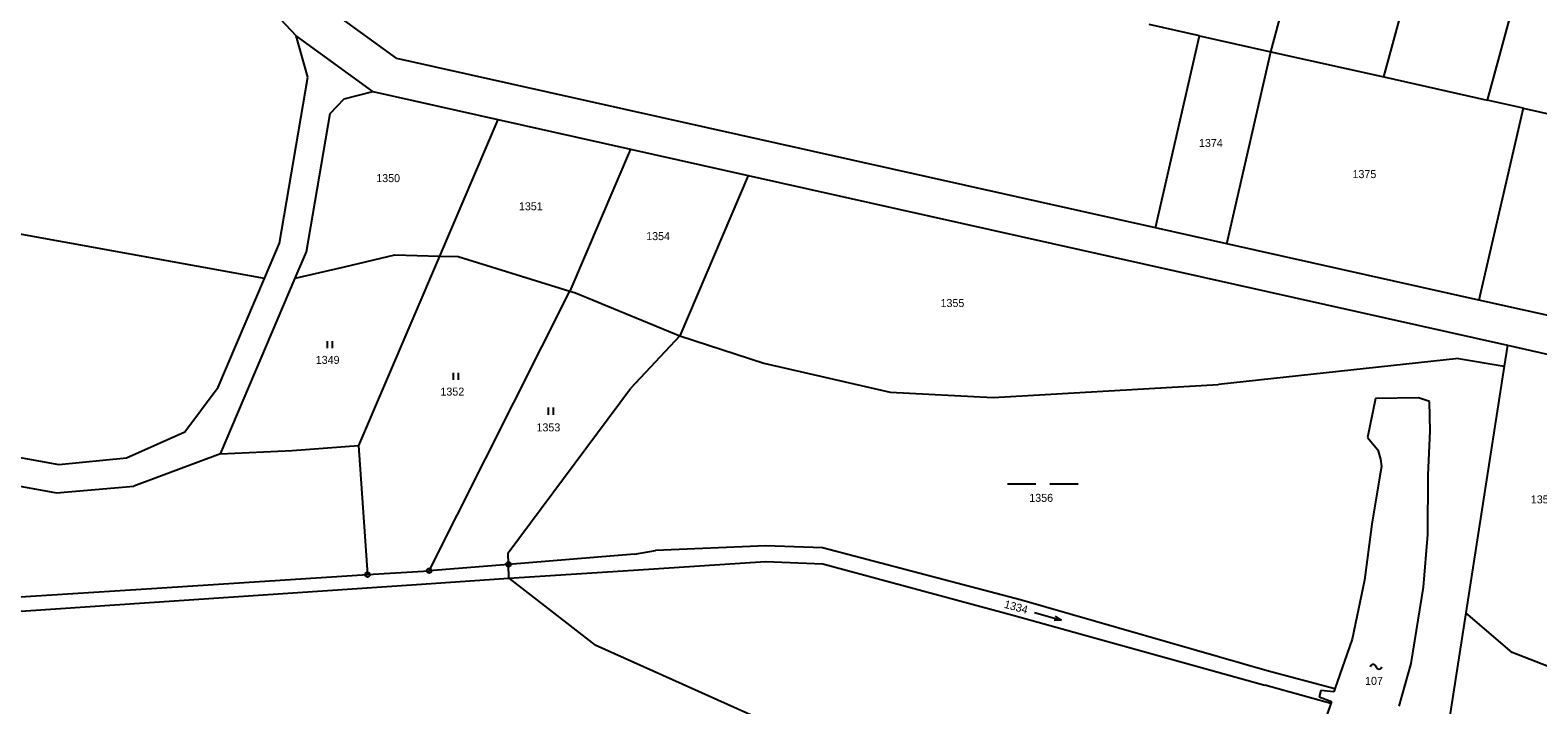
# Model space of a CAD drawing. Extents: x -796130 to -793145, y -1109506 to -1106267.
# Drawn here: x -795165.2 to -794845, y -1107731.2 to -1107587.8 of the extents above; entities that cross this region are included whole.
import ezdxf

# ---------------------------------------------------------------- set-up
doc = ezdxf.new("R2010")
doc.units = 0
for name, color, linetype in [('Vrstva 1', 7, 'Continuous'), ('Vrstva 14', 7, 'Continuous'), ('Vrstva 15', 7, 'Continuous'), ('Vrstva 23', 7, 'Continuous'), ('Vrstva 25', 7, 'Continuous'), ('Vrstva 28', 7, 'Continuous')]:
    doc.layers.add(name, color=color, linetype=linetype)

msp = doc.modelspace()

# ---------------------------------------------------------------- linework, layer by layer
at = {"layer": 'Vrstva 1'}
for p, q in [((-795151.06, -1107543.92), (-795108.76, -1107589.05)), ((-794901.69, -1107592.42), (-794889.91, -1107549.15)), ((-794877.66, -1107597.79), (-794866.67, -1107557.39)), ((-794845.65, -1107565.77), (-794855.7, -1107602.7)), ((-795087.38, -1107593.83), (-795105.91, -1107580.39)), ((-794916.83, -1107589.03), (-794927.52, -1107586.64)), ((-795092.45, -1107600.89), (-795108.76, -1107589.05)), ((-795106.26, -1107597.81), (-795108.76, -1107589.05)), ((-794926.2, -1107629.87), (-794916.83, -1107589.03)), ((-794916.83, -1107589.03), (-794901.69, -1107592.42)), ((-794911.06, -1107633.25), (-794901.69, -1107592.42)), ((-794901.69, -1107592.42), (-794877.66, -1107597.79)), ((-794926.2, -1107629.87), (-795087.38, -1107593.83)), ((-795112.31, -1107633.1), (-795106.26, -1107597.81)), ((-794877.66, -1107597.79), (-794855.7, -1107602.7)), ((-795101.49, -1107605.52), (-795098.55, -1107602.42)), ((-795098.55, -1107602.42), (-795092.45, -1107600.89)), ((-795092.45, -1107600.89), (-795065.91, -1107606.83)), ((-794848.09, -1107604.4), (-794855.7, -1107602.7)), ((-795106.54, -1107634.93), (-795101.49, -1107605.52)), ((-794848.09, -1107604.4), (-794857.47, -1107645.24)), ((-794848.09, -1107604.4), (-794833.09, -1107607.75)), ((-795115.49, -1107640.57), (-795290.5, -1107608.97)), ((-795065.91, -1107606.83), (-795078.3, -1107635.85)), ((-795065.91, -1107606.83), (-795037.74, -1107613.13)), ((-795037.74, -1107613.13), (-795050.62, -1107643.3)), ((-795037.74, -1107613.13), (-795012.7, -1107618.72)), ((-795012.7, -1107618.72), (-795027.25, -1107652.81)), ((-795012.7, -1107618.72), (-794851.43, -1107654.78)), ((-794911.06, -1107633.25), (-794926.2, -1107629.87)), ((-795115.49, -1107640.57), (-795112.31, -1107633.1)), ((-795108.93, -1107640.55), (-795106.54, -1107634.93)), ((-794857.47, -1107645.24), (-794911.06, -1107633.25)), ((-795108.93, -1107640.55), (-795098.46, -1107638.1)), ((-795098.46, -1107638.1), (-795087.74, -1107635.6)), ((-795078.3, -1107635.85), (-795095.47, -1107676.09)), ((-795087.74, -1107635.6), (-795078.3, -1107635.85)), ((-795078.3, -1107635.85), (-795074.32, -1107635.96)), ((-795074.32, -1107635.96), (-795050.62, -1107643.3)), ((-795125.33, -1107663.67), (-795115.49, -1107640.57)), ((-795124.84, -1107677.84), (-795108.93, -1107640.55)), ((-795080.51, -1107702.7), (-795050.62, -1107643.3)), ((-795050.62, -1107643.3), (-795049.42, -1107643.67)), ((-795049.42, -1107643.67), (-795027.25, -1107652.81)), ((-794804.82, -1107656.92), (-794857.47, -1107645.24)), ((-795312.81, -1107652.58), (-795159.16, -1107680.14)), ((-795027.25, -1107652.81), (-795037.71, -1107663.97)), ((-795027.25, -1107652.81), (-795009.41, -1107658.59)), ((-794861.81, -1107657.57), (-794912.83, -1107663.11)), ((-794861.81, -1107657.57), (-794852.12, -1107659.23)), ((-794851.43, -1107654.78), (-794852.12, -1107659.23)), ((-794851.43, -1107654.78), (-794822.97, -1107661.15)), ((-795009.41, -1107658.59), (-794982.58, -1107664.76)), ((-794852.12, -1107659.23), (-794860.27, -1107711.64)), ((-795283.03, -1107664.03), (-795159.63, -1107686.15)), ((-795132.41, -1107673.18), (-795125.33, -1107663.67)), ((-795063.7, -1107698.92), (-795037.71, -1107663.97)), ((-794960.66, -1107665.89), (-794912.83, -1107663.11)), ((-794982.58, -1107664.76), (-794960.66, -1107665.89)), ((-794879.42, -1107666.09), (-794881.15, -1107674.39)), ((-794870.3, -1107665.96), (-794879.42, -1107666.09)), ((-794867.97, -1107666.71), (-794870.3, -1107665.96)), ((-794867.85, -1107673.04), (-794867.97, -1107666.71)), ((-795144.79, -1107678.7), (-795132.41, -1107673.18)), ((-794868.28, -1107682.32), (-794867.85, -1107673.04)), ((-795109.6, -1107677.14), (-795095.47, -1107676.09)), ((-795095.47, -1107676.09), (-795093.58, -1107703.53)), ((-794881.15, -1107674.39), (-794878.98, -1107676.99)), ((-795159.16, -1107680.14), (-795144.79, -1107678.7)), ((-795124.84, -1107677.84), (-795143.24, -1107684.73)), ((-795124.84, -1107677.84), (-795109.6, -1107677.14)), ((-794878.98, -1107676.99), (-794878.38, -1107679.02)), ((-794878.38, -1107679.02), (-794878.14, -1107680.58)), ((-794878.63, -1107682.96), (-794880.22, -1107692.77)), ((-794878.14, -1107680.58), (-794878.63, -1107682.96)), ((-794868.32, -1107694.99), (-794868.28, -1107682.32)), ((-795159.63, -1107686.15), (-795143.24, -1107684.73)), ((-794880.22, -1107692.77), (-794881.82, -1107704.69)), ((-794869.27, -1107706.16), (-794868.32, -1107694.99)), ((-795063.64, -1107701.34), (-795063.7, -1107698.92)), ((-795036.87, -1107699.17), (-795063.64, -1107701.34)), ((-795036.87, -1107699.17), (-795032.41, -1107698.41)), ((-795008.97, -1107697.4), (-795032.41, -1107698.41)), ((-794996.93, -1107697.81), (-795008.97, -1107697.4)), ((-794954.66, -1107708.98), (-794996.93, -1107697.81)), ((-795063.64, -1107701.34), (-795080.51, -1107702.7)), ((-795063.57, -1107704.31), (-795063.64, -1107701.34)), ((-795037.05, -1107702.59), (-795009.06, -1107700.72)), ((-795009.06, -1107700.72), (-794996.83, -1107701.2)), ((-794996.83, -1107701.2), (-794956.2, -1107712.22)), ((-795174.26, -1107711.73), (-795083.2, -1107705.59)), ((-795138.32, -1107706.38), (-795093.58, -1107703.53)), ((-795093.58, -1107703.53), (-795080.51, -1107702.7)), ((-795083.2, -1107705.59), (-795063.57, -1107704.31)), ((-795063.57, -1107704.31), (-795037.05, -1107702.59)), ((-795063.57, -1107704.31), (-795045.21, -1107718.5)), ((-794881.82, -1107704.69), (-794884.37, -1107717.23)), ((-795169.54, -1107708.39), (-795138.32, -1107706.38)), ((-794871.84, -1107722.41), (-794869.27, -1107706.16)), ((-794902.44, -1107723.95), (-794954.66, -1107708.98)), ((-794860.27, -1107711.64), (-794863.8, -1107734.35)), ((-794850.4, -1107720.09), (-794860.27, -1107711.64)), ((-794956.2, -1107712.22), (-794902.94, -1107727.04)), ((-794884.37, -1107717.23), (-794888.08, -1107727.81)), ((-794971, -1107751.75), (-795045.21, -1107718.5)), ((-794837.64, -1107725.07), (-794850.4, -1107720.09)), ((-794888.08, -1107727.81), (-794902.44, -1107723.95)), ((-794874.41, -1107731.5), (-794871.84, -1107722.41)), ((-794888.92, -1107730.89), (-794902.94, -1107727.04)), ((-794888.08, -1107727.81), (-794888.29, -1107728.42)), ((-794888.92, -1107730.89), (-794892.98, -1107742.53)), ((-794891.09, -1107728.13), (-794891.45, -1107729.52)), ((-794891.45, -1107729.52), (-794888.78, -1107730.49)), ((-794888.29, -1107728.42), (-794891.09, -1107728.13)), ((-794888.78, -1107730.49), (-794888.92, -1107730.89))]:
    msp.add_line(p, q, dxfattribs=at)
at = {"layer": 'Vrstva 23'}
for p, q in [((-795102.06, -1107655.4), (-795102.06, -1107653.9)), ((-795101.06, -1107653.9), (-795101.06, -1107655.4)), ((-795075.34, -1107662.16), (-795075.34, -1107660.66)), ((-795074.34, -1107660.66), (-795074.34, -1107662.16)), ((-795055.11, -1107669.54), (-795055.11, -1107668.04)), ((-795054.11, -1107668.04), (-795054.11, -1107669.54)), ((-794957.61, -1107684.23), (-794951.61, -1107684.23)), ((-794948.61, -1107684.23), (-794942.61, -1107684.23)), ((-794951.91, -1107711.606), (-794946.129, -1107713.213)), ((-794946.129, -1107713.213), (-794947.708, -1107713.293)), ((-794946.129, -1107713.213), (-794947.44, -1107712.329))]:
    msp.add_line(p, q, dxfattribs=at)
at = {"layer": 'Vrstva 25'}
for centre, start, end in [((-794879.945, -1107723.251), 12.68038, 167.31961), ((-794878.695, -1107722.969), 192.68038, 347.31961)]:
    msp.add_arc(centre, 0.641, start, end, dxfattribs=at)
at = {"layer": 'Vrstva 28'}
for centre, radius in [((-795080.51, -1107702.7), 0.5), ((-795063.64, -1107701.34), 0.5), ((-795063.64, -1107701.34), 0.01), ((-795093.58, -1107703.53), 0.5), ((-795093.58, -1107703.53), 0.01), ((-795080.51, -1107702.7), 0.01)]:
    msp.add_circle(centre, radius, dxfattribs=at)

# ---------------------------------------------------------------- texts
at = {"layer": 'Vrstva 14'}
for s, p in [('1374', (-794916.952, -1107612.66)), ('1350', (-795091.725, -1107620.13)), ('1375', (-794884.333, -1107619.27)), ('1351', (-795061.419, -1107626.11)), ('1354', (-795034.382, -1107632.45)), ('1355', (-794971.852, -1107646.67)), ('1349', (-795104.576, -1107658.75)), ('1352', (-795078.086, -1107665.49)), ('1353', (-795057.686, -1107673.09)), ('1356', (-794952.996, -1107688.06)), ('1359', (-794846.456, -1107688.39))]:
    msp.add_text(s, height=1.7, dxfattribs=at).set_placement(p)
msp.add_text('1334', height=1.7, rotation=344.7, dxfattribs=at).set_placement((-794958.463, -1107710.54))
at = {"layer": 'Vrstva 15'}
msp.add_text('107', height=1.7, dxfattribs=at).set_placement((-794881.666, -1107726.95))

doc.saveas('drawing.dxf')
